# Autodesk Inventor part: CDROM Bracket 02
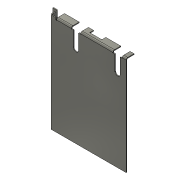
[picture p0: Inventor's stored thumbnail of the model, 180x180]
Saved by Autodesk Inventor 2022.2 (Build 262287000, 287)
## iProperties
Created: 2005-12
Material: アルミニウム 6061
Document SubType Name: Sheet Metal
Mass: 23.6854 g
Surface Area: 180.456 cm^2
Volume: 8.77235 cm^3
Density: 2.7 g/cm^3
Sheet Metal Rule: Default_mm
Appearance: Silicon Nitride - Polished
Flat Pattern Width: 8.68191 cm
Flat Pattern Length: 10.661 cm
Flat Pattern Area: 92.5575 cm^2
Sheet Metal Width: 86.819 mm
Sheet Metal Length: 106.610 mm
Sheet Metal Area: 9255.747 mm^2
Author: Autodesk, Inc.
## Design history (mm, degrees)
node "Contour Flange1"
  sketch "Sketch2"
    geometry: L1 (11, 25)-(16, 25); L2 (16, 25)-(16, 18); L3 (16, 18)-(92, 18)
    constraints: 6 end point, 1 parallel
    dimensions: "d1" = 90 deg angle of L2 L1; "d2" = 5 distance of L1.start L1.end; "d3" = 7 distance between parallel lines of L3 L1; "d22" = 81 horizontal distance of L3.end L1.start (computed from OPTIC_SLOT_)
node "Flange3"
sketch "Sketch5"
  geometry: L1 (15, -8)-(15, -2) reference; L2 (24, -2)-(24, -8) reference; L3 (14.8, 1.322)-(24.2, 1.322); L4 (24.2, 1.322)-(24.2, -8.678); L5 (24.2, -8.678)-(14.8, -8.678); L6 (14.8, -8.678)-(14.8, 1.322); L7 (16.8, -8.678)-(22.2, -8.678); L8 (22.2, -8.678)-(22.2, -23.678); L9 (22.2, -23.678)-(16.8, -23.678); L10 (16.8, -23.678)-(16.8, -8.678); 1 further point
  constraints: 20 end point, 4 parallel, 2 horizontal, 2 perpendicular, 2 vertical, 1 horizontal alignment, 1 midpoint, 1 point on line, 6 other
  dimensions: "d33" = 0.2 distance between parallel lines of L6 L1 (derived); "d34" = 0.2 distance between parallel lines of L4 L2 (derived); "d35" = 9.4 distance of L3.start L3.end; "d38" = 2 distance between parallel lines of L4 L8; "d39" = 2 distance between parallel lines of L10 L6 (= d38); "d40" = 15 distance between parallel lines of L9 L7; "d41" = 10 distance of L3.end L4.end
cut "Cut1" sketch "Sketch5" dims "d42" = 0.8 (= Thickness), "d43" = 0
sketch "Sketch6"
  geometry: L1 (-40.9, 6.4)-(-28.5, 6.4); L2 (-28.5, 6.4)-(-28.5, 2.4); L3 (-28.5, 2.4)-(-40.9, 2.4); L4 (-40.9, 2.4)-(-40.9, 6.4); L5 (-46, 6.4)-(-46, 0) reference
  constraints: 8 end point, 2 parallel, 1 horizontal, 1 perpendicular
  dimensions: "d49" = 4 distance of L1.end L2.end; "d62" = 5.1 distance between parallel lines of L5 L4; "d63" = 12.4 distance of L1.start L1.end
cut "Cut2" sketch "Sketch6" dims "d51" = 0.8 (= Thickness), "d52" = 0
pattern_linear "Rectangular Pattern2" dims "d66" = 42
body "Solid1"
face "Plate1" dims "d8" = 100, "d11" = 1.6 (= MinimumRemnant), "d13" = 0.8 (= BendRadius), "d14" = 1, "d67" = 0.8 (= Thickness), "SeamGap" = 0.01
bend "Bend1" dims "d9" = 0.8 (= BendReliefWidth), "d10" = 0.4 (= BendReliefDepth), "d11" = 1.6 (= MinimumRemnant), "d12" = 0.8 (= BendRadius), "d13" = 0.8 (= BendRadius), "d14" = 1, "d67" = 0.8 (= Thickness), "SeamGap" = 0.01
sketch "Sketch7"
  geometry: L1 (-5, 0)-(-75.2, 0); L2 (-75.2, 0)-(-75.2, 8); L3 (-75.2, 8)-(-5, 8); L4 (-5, 8)-(-5, 0)
  constraints: 8 end point
face "Plate4" dims "d53" = 0, "d54" = 5, "d57" = 1.6 (= MinimumRemnant), "d59" = 8, "d60" = 90 deg, "d61" = 0.8 (= BendRadius), "d67" = 0.8 (= Thickness), "SeamGap" = 0.01
bend "Bend4" dims "d55" = 0.8 (= BendReliefWidth), "d56" = 0.4 (= BendReliefDepth), "d57" = 1.6 (= MinimumRemnant), "d58" = 0.8 (= BendRadius), "d59" = 8, "d60" = 90 deg, "d61" = 0.8 (= BendRadius), "d67" = 0.8 (= Thickness), "SeamGap" = 0.01
feature "定義1"
other parameters: "Thickness" = 0.8 (derived), "BendRadius" = 0.8 (= Thickness), "BendReliefWidth" = 0.8 (= Thickness), "BendReliefDepth" = 0.4 (= 0.5 x Thickness), "CornerReliefSize" = 3.2 (= 4 x Thickness), "MinimumRemnant" = 1.6 (= 2 x Thickness), "TransitionRadius" = 0.8 (= BendRadius), "JacobiRadiusSize" = 0.8 (= BendRadius), "GapSize" = 0.8 (= Thickness), "BendRadius" = 0.8, "BendReliefDepth" = 0.4, "BendReliefWidth" = 0.8, "CornerReliefSize" = 3.2, "GapSize" = 0.8, "JacobiRadiusSize" = 0.8, "MinimumRemnant" = 1.6, "Thickness" = 0.8, "TransitionRadius" = 0.8
